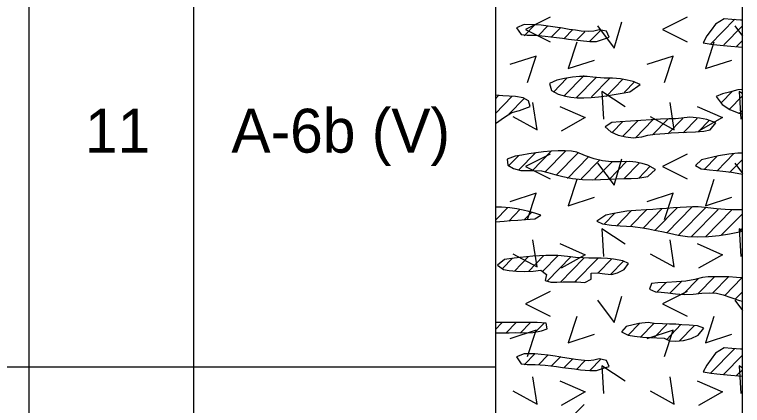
# Model space of a CAD drawing. Extents: x 0 to 0.83, y -0.65 to 1.27.
# Drawn here: x 0.7228 to 0.8333, y 0.2811 to 0.3405 of the extents above; entities that cross this region are included whole.
import ezdxf

# ---------------------------------------------------------------- set-up
doc = ezdxf.new("R2010")
doc.units = 0

msp = doc.modelspace()

# ---------------------------------------------------------------- linework, layer by layer
for points in [[(0, 0), (0.83333, 0), (0.83333, 1.275), (0, 1.275)], [(0, 0), (0.83333, 0), (0.83333, 1.275), (0, 1.275)], [(0, 0), (0.83333, 0), (0.83333, 1.275), (0, 1.275)], [(0, 0), (0.83333, 0), (0.83333, 1.275), (0, 1.275)], [(0, 0), (0.83333, 0), (0.83333, 1.275), (0, 1.275)], [(0.83305, 0.33968), (0.83171, 0.33979), (0.83054, 0.33989), (0.82925, 0.33907), (0.82857, 0.33816), (0.82792, 0.33727), (0.82735, 0.33624), (0.82858, 0.33602), (0.82945, 0.33592), (0.83045, 0.33582), (0.83155, 0.33573), (0.83272, 0.33563), (0.83333, 0.33558), (0.83333, 0.33967)], [(0.80066, 0.33738), (0.80188, 0.33737), (0.80339, 0.33724), (0.80423, 0.33715), (0.8051, 0.33704), (0.806, 0.33692), (0.80692, 0.3368), (0.80784, 0.33668), (0.80875, 0.33657), (0.81014, 0.33643), (0.81119, 0.33644), (0.81222, 0.33678), (0.81308, 0.33707), (0.81267, 0.33797), (0.8116, 0.33822), (0.81075, 0.33802), (0.80989, 0.33794), (0.80885, 0.33802), (0.80799, 0.33813), (0.80703, 0.33827), (0.806, 0.33844), (0.80492, 0.3386), (0.80384, 0.33876), (0.8028, 0.33889), (0.80182, 0.33898), (0.8002, 0.33899), (0.79901, 0.33852), (0.79974, 0.33748)], [(0.81233, 0.33087), (0.81063, 0.33099), (0.80977, 0.33112), (0.8086, 0.33113), (0.80755, 0.33099), (0.80632, 0.33079), (0.80513, 0.33054), (0.80403, 0.33002), (0.80436, 0.32896), (0.80536, 0.3284), (0.80647, 0.3281), (0.8073, 0.32795), (0.80824, 0.32787), (0.80926, 0.32786), (0.81035, 0.32791), (0.81149, 0.32801), (0.81267, 0.32816), (0.81386, 0.32835), (0.81506, 0.32856), (0.81625, 0.32879), (0.81783, 0.32987), (0.81673, 0.33037), (0.81585, 0.33057), (0.8148, 0.33073), (0.81361, 0.33083)], [(0.79583, 0.32396), (0.79719, 0.32495), (0.79831, 0.32565), (0.79951, 0.32593), (0.80111, 0.32653), (0.80086, 0.32741), (0.80002, 0.32789), (0.79889, 0.32808), (0.79791, 0.32811), (0.79694, 0.32817), (0.79583, 0.32825)], [(0.83265, 0.32906), (0.83136, 0.32875), (0.83028, 0.32847), (0.82934, 0.32808), (0.83026, 0.32688), (0.83142, 0.32612), (0.83279, 0.32554), (0.83333, 0.32544), (0.83333, 0.32915)], [(0.82537, 0.32491), (0.82408, 0.32476), (0.82319, 0.3247), (0.82214, 0.32467), (0.82091, 0.32464), (0.81947, 0.32454), (0.81792, 0.32442), (0.81632, 0.3243), (0.81475, 0.32421), (0.81348, 0.32411), (0.81247, 0.32347), (0.81337, 0.32271), (0.81444, 0.32221), (0.81561, 0.32192), (0.81675, 0.32181), (0.81807, 0.32193), (0.81896, 0.3222), (0.82003, 0.32235), (0.82157, 0.32247), (0.82253, 0.32253), (0.82362, 0.32258), (0.82483, 0.32265), (0.82618, 0.32271), (0.82745, 0.32282), (0.82842, 0.32299), (0.82927, 0.32405), (0.82791, 0.32457), (0.82679, 0.32477)], [(0.79885, 0.319), (0.79763, 0.31854), (0.79773, 0.31764), (0.79859, 0.31712), (0.7997, 0.31682), (0.80074, 0.31683), (0.80165, 0.31684), (0.80281, 0.31676), (0.80377, 0.31655), (0.80486, 0.3162), (0.80606, 0.31591), (0.80751, 0.31563), (0.80905, 0.31545), (0.81052, 0.31542), (0.81177, 0.31547), (0.81289, 0.31551), (0.81408, 0.31555), (0.81553, 0.31559), (0.81642, 0.31562), (0.81745, 0.31565), (0.81897, 0.31592), (0.82011, 0.31696), (0.81896, 0.31763), (0.8181, 0.31789), (0.81717, 0.31809), (0.81626, 0.31819), (0.81479, 0.31814), (0.81343, 0.31814), (0.8121, 0.31829), (0.8108, 0.31859), (0.80953, 0.31905), (0.8082, 0.3196), (0.80736, 0.31976), (0.8064, 0.31984), (0.80536, 0.31984), (0.80427, 0.31978), (0.80314, 0.31967), (0.80201, 0.31952), (0.8009, 0.31935), (0.79984, 0.31917)], [(0.83263, 0.31944), (0.83126, 0.31931), (0.82969, 0.31904), (0.82883, 0.31887), (0.82712, 0.31846), (0.82623, 0.31759), (0.82708, 0.3171), (0.82831, 0.31691), (0.82941, 0.31684), (0.83033, 0.31675), (0.83165, 0.31657), (0.83253, 0.31643), (0.83333, 0.31629), (0.83333, 0.31944)], [(0.79583, 0.30904), (0.79715, 0.30915), (0.79814, 0.30922), (0.79922, 0.3093), (0.80039, 0.30939), (0.80179, 0.30951), (0.80275, 0.31002), (0.80179, 0.31036), (0.80091, 0.31058), (0.80003, 0.3108), (0.79909, 0.31101), (0.79803, 0.31117), (0.79677, 0.31127), (0.79583, 0.31125)], [(0.82816, 0.30679), (0.82978, 0.30696), (0.83137, 0.30721), (0.8329, 0.30752), (0.83333, 0.30763), (0.83333, 0.31087), (0.83295, 0.31084), (0.83188, 0.31086), (0.83071, 0.31091), (0.82938, 0.31101), (0.82807, 0.31118), (0.82662, 0.3113), (0.82576, 0.3113), (0.82484, 0.31128), (0.82387, 0.31123), (0.82286, 0.31116), (0.82182, 0.31108), (0.82077, 0.31099), (0.81973, 0.31091), (0.81872, 0.31084), (0.81715, 0.31074), (0.81579, 0.31065), (0.81491, 0.31052), (0.81357, 0.31024), (0.8126, 0.31003), (0.81121, 0.30911), (0.8121, 0.30875), (0.81345, 0.3085), (0.81479, 0.30841), (0.81668, 0.30831), (0.81818, 0.30811), (0.81905, 0.30796), (0.82, 0.30778), (0.82107, 0.30757), (0.82225, 0.30732), (0.82357, 0.30703), (0.82501, 0.3068), (0.82656, 0.30673)], [(0.79708, 0.30181), (0.79794, 0.30163), (0.79904, 0.30152), (0.80028, 0.30149), (0.80156, 0.30154), (0.80274, 0.3017), (0.80361, 0.30103), (0.80338, 0.30014), (0.80422, 0.29987), (0.80517, 0.29985), (0.80613, 0.2999), (0.8072, 0.29993), (0.80818, 0.2999), (0.80939, 0.29983), (0.81037, 0.3003), (0.81038, 0.30124), (0.8113, 0.3013), (0.81244, 0.30112), (0.81346, 0.30101), (0.81438, 0.30127), (0.81539, 0.30181), (0.81601, 0.30272), (0.81517, 0.3031), (0.81374, 0.30337), (0.81285, 0.30346), (0.81187, 0.30352), (0.81, 0.30352), (0.8091, 0.30354), (0.808, 0.30362), (0.80678, 0.30377), (0.8053, 0.3039), (0.80443, 0.30392), (0.80349, 0.3039), (0.80251, 0.30386), (0.80152, 0.3038), (0.80054, 0.30372), (0.79959, 0.30363), (0.7987, 0.30353), (0.79722, 0.30331), (0.79614, 0.30243)], [(0.83241, 0.30059), (0.83129, 0.30066), (0.83017, 0.30069), (0.8291, 0.30069), (0.82811, 0.30066), (0.82728, 0.30057), (0.82608, 0.30027), (0.82476, 0.30004), (0.8233, 0.29991), (0.82183, 0.29982), (0.82051, 0.29976), (0.81951, 0.29967), (0.81922, 0.2988), (0.82013, 0.29838), (0.82097, 0.29833), (0.822, 0.29823), (0.82318, 0.2981), (0.82448, 0.29801), (0.82584, 0.29804), (0.82719, 0.2982), (0.82836, 0.29827), (0.8294, 0.29819), (0.83043, 0.29795), (0.83156, 0.29756), (0.83291, 0.29707), (0.83333, 0.297), (0.83333, 0.30052)], [(0.79583, 0.29218), (0.79676, 0.29217), (0.79792, 0.29219), (0.79882, 0.29223), (0.79992, 0.29218), (0.80151, 0.29223), (0.80282, 0.29248), (0.80367, 0.2928), (0.80354, 0.29364), (0.80216, 0.29373), (0.79583, 0.29373)], [(0.81822, 0.29153), (0.81944, 0.29147), (0.82033, 0.29143), (0.82145, 0.29137), (0.82229, 0.29095), (0.82324, 0.29091), (0.82438, 0.29101), (0.82555, 0.2913), (0.82662, 0.29181), (0.82749, 0.2929), (0.82651, 0.29321), (0.82524, 0.29331), (0.82413, 0.29337), (0.82324, 0.29348), (0.82226, 0.2935), (0.82121, 0.29352), (0.81995, 0.29361), (0.81902, 0.29373), (0.81761, 0.29359), (0.81566, 0.29314), (0.81496, 0.29231), (0.81598, 0.29182), (0.81695, 0.29164)], [(0.83305, 0.28968), (0.83171, 0.28979), (0.83054, 0.28989), (0.82925, 0.28907), (0.82857, 0.28816), (0.82792, 0.28727), (0.82735, 0.28624), (0.82858, 0.28602), (0.82945, 0.28592), (0.83045, 0.28582), (0.83155, 0.28573), (0.83272, 0.28563), (0.83333, 0.28558), (0.83333, 0.28967)], [(0.80066, 0.28738), (0.80188, 0.28737), (0.80339, 0.28724), (0.80423, 0.28715), (0.8051, 0.28704), (0.806, 0.28692), (0.80692, 0.2868), (0.80784, 0.28668), (0.80875, 0.28657), (0.81014, 0.28643), (0.81119, 0.28644), (0.81222, 0.28678), (0.81308, 0.28707), (0.81267, 0.28797), (0.8116, 0.28822), (0.81075, 0.28802), (0.80989, 0.28794), (0.80885, 0.28802), (0.80799, 0.28813), (0.80703, 0.28827), (0.806, 0.28844), (0.80492, 0.2886), (0.80384, 0.28876), (0.8028, 0.28889), (0.80182, 0.28898), (0.8002, 0.28899), (0.79901, 0.28852), (0.79974, 0.28748)]]:
    msp.add_lwpolyline(points, close=True)
for points in [[(0.725, 1.22083), (0.725, -0.64575)], [(0.75, 1.22083), (0.75, -0.64575)], [(0.75, 1.22083), (0.75, -0.64575)], [(0.79583, 1.22083), (0.79583, -0.64575)], [(0.725, 1.20833), (0.725, -0.64575)], [(0.83333, -0.64575), (0.83333, 1.13365)], [(0.80412, 0.34013), (0.80038, 0.33826), (0.80412, 0.33638)], [(0.81134, 0.33879), (0.81384, 0.33541), (0.81503, 0.33941)], [(0.82496, 0.34013), (0.82121, 0.33826), (0.82496, 0.33638)], [(0.83217, 0.33981), (0.82844, 0.33599)], [(0.80188, 0.33903), (0.8002, 0.33731)], [(0.8038, 0.33879), (0.80237, 0.33732)], [(0.80575, 0.33857), (0.80429, 0.33708)], [(0.80758, 0.33824), (0.80627, 0.33689)], [(0.81188, 0.33821), (0.81016, 0.33646)], [(0.83333, 0.33879), (0.83052, 0.33591)], [(0.83217, 0.33879), (0.83333, 0.33723)], [(0.80941, 0.3379), (0.80816, 0.33662)], [(0.80818, 0.3363), (0.80687, 0.3323), (0.81087, 0.33361)], [(0.82901, 0.3363), (0.8277, 0.3323), (0.8317, 0.33361)], [(0.83333, 0.33657), (0.83245, 0.33567)], [(0.80069, 0.33022), (0.802, 0.33422), (0.798, 0.33291)], [(0.82152, 0.33022), (0.82284, 0.33422), (0.81884, 0.33291)], [(0.80465, 0.32875), (0.80667, 0.33083)], [(0.80626, 0.32819), (0.80928, 0.33128)], [(0.80809, 0.32785), (0.81111, 0.33095)], [(0.81041, 0.32802), (0.81318, 0.33085)], [(0.81264, 0.32809), (0.81518, 0.33069)], [(0.81536, 0.32867), (0.81699, 0.33033)], [(0.7963, 0.32821), (0.79583, 0.32772)], [(0.81551, 0.32649), (0.81201, 0.32881), (0.81226, 0.32462)], [(0.8301, 0.32709), (0.83184, 0.32887)], [(0.83131, 0.32612), (0.83333, 0.32819)], [(0.83333, 0.32848), (0.83284, 0.32881), (0.83309, 0.32462)], [(0.79834, 0.32808), (0.79583, 0.32551)], [(0.79786, 0.32538), (0.80023, 0.32781)], [(0.79847, 0.32501), (0.80215, 0.32301), (0.80153, 0.32714)], [(0.8193, 0.32501), (0.82299, 0.32301), (0.82236, 0.32714)], [(0.80562, 0.32656), (0.80946, 0.32487), (0.80581, 0.32281)], [(0.82645, 0.32656), (0.83029, 0.32487), (0.82664, 0.32281)], [(0.83285, 0.32549), (0.83333, 0.32598)], [(0.81519, 0.32428), (0.81354, 0.32258)], [(0.81514, 0.32201), (0.81748, 0.32441)], [(0.81709, 0.3218), (0.81974, 0.32451)], [(0.8197, 0.32225), (0.82203, 0.32465)], [(0.82202, 0.32242), (0.8243, 0.32475)], [(0.82431, 0.32255), (0.82644, 0.32474)], [(0.82663, 0.32271), (0.82834, 0.32447)], [(0.79933, 0.31687), (0.80195, 0.31956)], [(0.80142, 0.3168), (0.8043, 0.31975)], [(0.80653, 0.31983), (0.8034, 0.31661)], [(0.80506, 0.3161), (0.8084, 0.31952)], [(0.83203, 0.31939), (0.82949, 0.31679)], [(0.79938, 0.31913), (0.79786, 0.31758)], [(0.80412, 0.3193), (0.80038, 0.31742), (0.80412, 0.31555)], [(0.80997, 0.31893), (0.80675, 0.31562)], [(0.81164, 0.31842), (0.80884, 0.31556)], [(0.81134, 0.31796), (0.81384, 0.31458), (0.81503, 0.31858)], [(0.81303, 0.31542), (0.81579, 0.31825)], [(0.82496, 0.3193), (0.82121, 0.31742), (0.82496, 0.31555)], [(0.82751, 0.31698), (0.82945, 0.31896)], [(0.83138, 0.31652), (0.83333, 0.31852)], [(0.81353, 0.31814), (0.81094, 0.31549)], [(0.81534, 0.31558), (0.81768, 0.31797)], [(0.8176, 0.31568), (0.81934, 0.31747)], [(0.83217, 0.31796), (0.83333, 0.31639)], [(0.83333, 0.3163), (0.83333, 0.31631)], [(0.80818, 0.31547), (0.80687, 0.31147), (0.81087, 0.31278)], [(0.82901, 0.31547), (0.8277, 0.31147), (0.8317, 0.31278)], [(0.80069, 0.30939), (0.802, 0.31339), (0.798, 0.31207)], [(0.82152, 0.30939), (0.82284, 0.31339), (0.81884, 0.31207)], [(0.79765, 0.31115), (0.79583, 0.30928)], [(0.7996, 0.31094), (0.79786, 0.30915)], [(0.8143, 0.30848), (0.8165, 0.31073)], [(0.8164, 0.30841), (0.81879, 0.31086)], [(0.81829, 0.30813), (0.82114, 0.31105)], [(0.82004, 0.30771), (0.82346, 0.31122)], [(0.82569, 0.31129), (0.82184, 0.30735)], [(0.82775, 0.31119), (0.8237, 0.30705)], [(0.82964, 0.31092), (0.82557, 0.30674)], [(0.83173, 0.31085), (0.82774, 0.30676)], [(0.8013, 0.31046), (0.80027, 0.30941)], [(0.81392, 0.3103), (0.81235, 0.30869)], [(0.83333, 0.31027), (0.83012, 0.30698)], [(0.81551, 0.30566), (0.81201, 0.30797), (0.81226, 0.30378)], [(0.83281, 0.30752), (0.83333, 0.30806)], [(0.83333, 0.30765), (0.83284, 0.30797), (0.83309, 0.30378)], [(0.79847, 0.30418), (0.80215, 0.30218), (0.80153, 0.3063)], [(0.8193, 0.30418), (0.82299, 0.30218), (0.82236, 0.3063)], [(0.80562, 0.30572), (0.80946, 0.30404), (0.80581, 0.30198)], [(0.82645, 0.30572), (0.83029, 0.30404), (0.82664, 0.30198)], [(0.80534, 0.30392), (0.80299, 0.30151)], [(0.79844, 0.30349), (0.79691, 0.30192)], [(0.79871, 0.30155), (0.80085, 0.30374)], [(0.80083, 0.30151), (0.80311, 0.30385)], [(0.80367, 0.3), (0.80732, 0.30374)], [(0.80571, 0.29988), (0.80924, 0.30349)], [(0.81142, 0.30351), (0.80785, 0.29986)], [(0.81141, 0.30129), (0.81348, 0.30341)], [(0.81528, 0.30305), (0.81331, 0.30103)], [(0.82909, 0.30069), (0.82656, 0.2981)], [(0.82885, 0.29823), (0.83122, 0.30066)], [(0.82035, 0.29837), (0.82176, 0.29982)], [(0.82233, 0.29819), (0.82408, 0.29998)], [(0.82433, 0.29802), (0.82666, 0.30041)], [(0.83325, 0.30052), (0.83065, 0.29786)], [(0.80412, 0.29846), (0.80038, 0.29659), (0.80412, 0.29471)], [(0.82496, 0.29846), (0.82121, 0.29659), (0.82496, 0.29471)], [(0.83333, 0.2984), (0.83227, 0.29731)], [(0.81134, 0.29712), (0.81384, 0.29375), (0.81503, 0.29775)], [(0.83217, 0.29712), (0.83333, 0.29556)], [(0.80818, 0.29463), (0.80687, 0.29063), (0.81087, 0.29195)], [(0.82901, 0.29463), (0.8277, 0.29063), (0.8317, 0.29195)], [(0.79583, 0.2927), (0.79681, 0.2937)], [(0.79898, 0.29372), (0.79747, 0.29217)], [(0.80116, 0.29373), (0.79959, 0.29213)], [(0.80328, 0.29369), (0.80188, 0.29226)], [(0.8177, 0.29359), (0.81596, 0.29181)], [(0.81988, 0.29361), (0.81785, 0.29153)], [(0.82185, 0.29342), (0.81997, 0.29149)], [(0.824, 0.29341), (0.82178, 0.29113)], [(0.82601, 0.29325), (0.82378, 0.29097)], [(0.80069, 0.28855), (0.802, 0.29255), (0.798, 0.29124)], [(0.82152, 0.28855), (0.82284, 0.29255), (0.81884, 0.29124)], [(0.83217, 0.28981), (0.82844, 0.28599)], [(0.80188, 0.28903), (0.8002, 0.28731)], [(0.8038, 0.28879), (0.80237, 0.28732)], [(0.80575, 0.28857), (0.80429, 0.28708)], [(0.83333, 0.28879), (0.83052, 0.28591)], [(0.80758, 0.28824), (0.80627, 0.28689)], [(0.80941, 0.2879), (0.80816, 0.28662)], [(0.81188, 0.28821), (0.81016, 0.28646)], [(0.70417, 0.287), (0.725, 0.287)], [(0.725, 0.287), (0.75, 0.287)], [(0.75, 0.287), (0.79583, 0.287)], [(0.81551, 0.28483), (0.81201, 0.28714), (0.81226, 0.28295)], [(0.83333, 0.28657), (0.83245, 0.28567)], [(0.83333, 0.28682), (0.83284, 0.28714), (0.83309, 0.28295)], [(0.79847, 0.28334), (0.80215, 0.28134), (0.80153, 0.28547)], [(0.8193, 0.28334), (0.82299, 0.28134), (0.82236, 0.28547)], [(0.80562, 0.28489), (0.80946, 0.28321), (0.80581, 0.28114)], [(0.82645, 0.28489), (0.83029, 0.28321), (0.82664, 0.28114)], [(0.80626, 0.27819), (0.80928, 0.28128)]]:
    msp.add_lwpolyline(points)

# ---------------------------------------------------------------- texts
for s, p in [('11', (0.73352, 0.31954)), ('A-6b (V)', (0.75575, 0.31954))]:
    msp.add_text(s, height=0.006667).set_placement(p)

doc.saveas('drawing.dxf')
